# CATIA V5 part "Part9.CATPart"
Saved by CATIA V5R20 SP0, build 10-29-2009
Part number: 1DIN7984516_DIN 7984 - M5 x 16 --- 16C
Revision: ANY
Definition: UNKNOWN
Nomenclature: 1DIN7984516_DIN 7984 - M5 x 16 --- 16C
Source: Unknown
Bounding box of the stored display mesh (mm): x 0 to 19.5, y -4.25 to 4.25, z -4.25 to 4.25
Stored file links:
  C:\Users\Utente\Desktop\IO LAVORO\3D X SITO CF\CUMSA\3D files PW\pw081230\pw081230_injection\Part9.CATPart
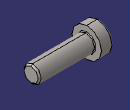
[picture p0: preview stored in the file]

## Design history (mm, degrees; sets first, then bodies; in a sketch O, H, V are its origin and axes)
Body1 "Hex" (main body)
  Solid1: solid without history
